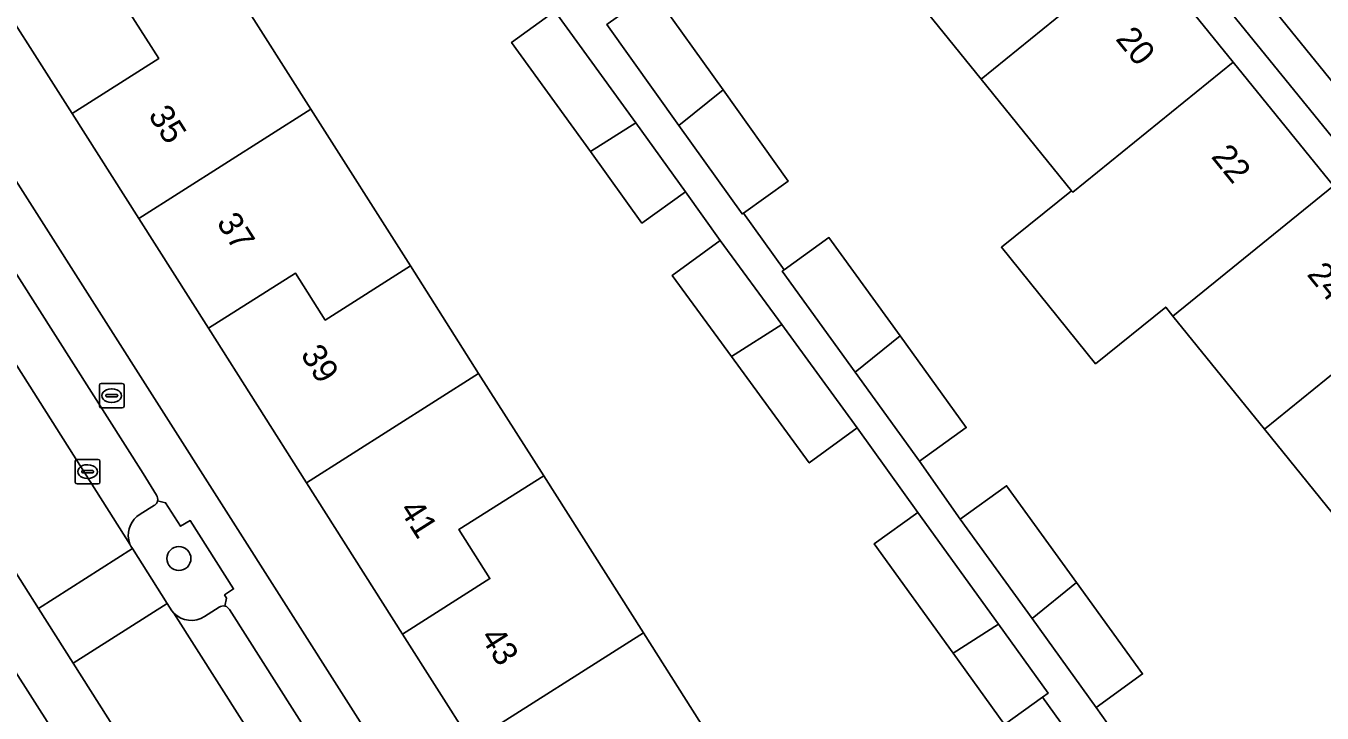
# Model space of a CAD drawing. Extents: x 162344 to 162869, y 381217 to 381818.
# Drawn here: x 162502.3 to 162555.1, y 381598.8 to 381626.8 of the extents above; entities that cross this region are included whole.
import ezdxf

# ---------------------------------------------------------------- set-up
doc = ezdxf.new("R2010")
doc.units = 0
for name, color, linetype in [('IMGEO_Boom', 7, 'Continuous'), ('IMGEO_Brandkraan', 7, 'Continuous'), ('IMGEO_Erf', 7, 'Continuous'), ('IMGEO_Groenvoorziening', 7, 'Continuous'), ('IMGEO_Kolk', 7, 'Continuous'), ('IMGEO_Pand', 7, 'Continuous'), ('IMGEO_Pand_nummerreeks', 7, 'Continuous'), ('IMGEO_Parkeervlak_open', 7, 'Continuous'), ('IMGEO_Rijbaan_lokaal_gesloten', 7, 'Continuous'), ('IMGEO_Rijbaan_lokaal_open', 7, 'Continuous'), ('IMGEO_Voetpad_open', 7, 'Continuous')]:
    doc.layers.add(name, color=color, linetype=linetype)

msp = doc.modelspace()

# ---------------------------------------------------------------- linework, layer by layer
at = {"layer": 'IMGEO_Boom'}
msp.add_circle((162508.528, 381605.122), 0.489, dxfattribs=at)
at = {"layer": 'IMGEO_Brandkraan'}
for p, q in [((162505.293, 381611.33), (162505.293, 381612.182)), ((162505.368, 381612.256), (162506.22, 381612.256)), ((162505.781, 381612.036), (162505.806, 381612.036)), ((162506.294, 381612.182), (162506.294, 381611.33)), ((162505.552, 381611.75), (162505.552, 381611.762)), ((162505.99, 381611.713), (162505.592, 381611.713)), ((162505.595, 381611.799), (162505.993, 381611.799)), ((162505.804, 381611.476), (162505.779, 381611.476)), ((162506.036, 381611.762), (162506.036, 381611.75)), ((162506.22, 381611.256), (162505.368, 381611.256))]:
    msp.add_line(p, q, dxfattribs=at)
for points in [[(162505.293, 381611.33), (162505.293, 381612.182)], [(162505.368, 381612.256), (162506.22, 381612.256)], [(162506.294, 381612.182), (162506.294, 381611.33)], [(162506.22, 381611.256), (162505.368, 381611.256)]]:
    msp.add_lwpolyline(points, dxfattribs=at)
for centre, radius, start, end in [((162505.37, 381612.18), 0.0765, 91.552, 178.448), ((162505.37, 381612.18), 0.0765, 91.552, 178.448), ((162506.218, 381612.18), 0.0765, 1.552, 88.448), ((162506.218, 381612.18), 0.0765, 1.552, 88.448), ((162505.592, 381611.759), 0.0403, 85.8775, 175.7526), ((162505.589, 381611.749), 0.0366, 178.938, 274.7102), ((162505.993, 381611.756), 0.043, 264.8664, 352.4533), ((162505.997, 381611.761), 0.0386, 1.7309, 96.639), ((162505.37, 381611.332), 0.0765, 181.552, 268.448), ((162505.37, 381611.332), 0.0765, 181.552, 268.448), ((162506.218, 381611.332), 0.0765, 271.552, 358.448), ((162506.218, 381611.332), 0.0765, 271.552, 358.448)]:
    msp.add_arc(centre, radius, start, end, dxfattribs=at)
for centre, major_axis, ratio, start_param, end_param in [((162505.78, 381611.756), (-0.387, 0.002), 0.722429, 4.712389, 7.853982), ((162505.805, 381611.756), (-0.39, 0.002), 0.717154, 1.570796, 4.712389)]:
    msp.add_ellipse(centre, major_axis=major_axis, ratio=ratio, start_param=start_param, end_param=end_param, dxfattribs=at)
at = {"layer": 'IMGEO_Erf'}
for points in [[(162513.38, 381674.107), (162512.565, 381673.447), (162516.63, 381668.417), (162520.622, 381663.477), (162524.355, 381658.858), (162528.316, 381653.955), (162532.138, 381649.227), (162536.056, 381644.377), (162539.798, 381639.748), (162543.769, 381634.833), (162547.709, 381629.957), (162551.438, 381625.343), (162555.512, 381620.301), (162559.239, 381615.69), (162563.247, 381610.73), (162566.934, 381606.168), (162570.843, 381601.33), (162571.832, 381602.129)], [(162509.729, 381614.501), (162506.891, 381618.974), (162504.179, 381623.249), (162500.254, 381629.436), (162496.21, 381635.81), (162493.518, 381640.054), (162490.785, 381644.361), (162486.625, 381650.919), (162483.717, 381649.074), (162500, 381623.471), (162531.035, 381574.671), (162533.863, 381576.458), (162531.166, 381580.71), (162527.169, 381587.01), (162523.206, 381593.256), (162520.428, 381597.636), (162517.63, 381602.045), (162513.719, 381608.21)], [(162500, 381603.428), (162482.857, 381630.326), (162481.918, 381629.814), (162481.958, 381629.752), (162482.007, 381629.783), (162485.338, 381624.533), (162488.628, 381619.345), (162491.92, 381614.157), (162495.211, 381608.969), (162498.502, 381603.78), (162501.793, 381598.593), (162505.084, 381593.404), (162508.375, 381588.216), (162511.667, 381583.028), (162514.958, 381577.839), (162518.25, 381572.651), (162521.79, 381567.07), (162522.773, 381567.696), (162522.094, 381568.761)]]:
    msp.add_lwpolyline(points, close=True, dxfattribs=at)
for points in [[(162509.92, 381629.7), (162513.898, 381623.43), (162517.95, 381617.043), (162520.727, 381612.666), (162523.373, 381608.497), (162527.437, 381602.092), (162531.429, 381595.8)], [(162556.718, 381605.428), (162552.71, 381610.388), (162548.983, 381614.999), (162548.688, 381615.364), (162545.837, 381613.06), (162542.005, 381617.803), (162544.856, 381620.107), (162541.181, 381624.654), (162537.239, 381629.531)], [(162527.821, 381628.216), (162530.674, 381624.218), (162533.328, 381620.5), (162531.501, 381619.196), (162533.154, 381616.877), (162534.984, 381618.198), (162537.875, 381614.19), (162540.57, 381610.455), (162538.67, 381609.084), (162540.325, 381606.725), (162542.212, 381608.087), (162545.056, 381604.145), (162547.745, 381600.418), (162545.859, 381599.057), (162547.476, 381596.777), (162549.379, 381598.143), (162552.266, 381594.122), (162554.849, 381590.523), (162555.13, 381590.715)], [(162545.066, 381597.532), (162543.669, 381599.469), (162542.134, 381598.362), (162540.035, 381601.272), (162536.826, 381605.721), (162538.594, 381606.997), (162536.135, 381610.447), (162534.179, 381609.019), (162531.014, 381613.356), (162528.606, 381616.655), (162530.562, 381618.083), (162529.142, 381620.065), (162527.374, 381618.79), (162525.275, 381621.701), (162522.066, 381626.149), (162523.834, 381627.425)]]:
    msp.add_lwpolyline(points, dxfattribs=at)
at = {"layer": 'IMGEO_Groenvoorziening'}
for points in [[(162507.534, 381607.289), (162506.945, 381606.925)], [(162508.988, 381606.666), (162508.597, 381606.435), (162507.987, 381607.394), (162507.655, 381607.466)], [(162510.402, 381603.182), (162510.461, 381603.501), (162510.386, 381603.641), (162510.756, 381603.885), (162508.988, 381606.666)], [(162506.486, 381605.887), (162506.536, 381605.712), (162506.577, 381605.621), (162506.636, 381605.528), (162508.054, 381603.286), (162508.241, 381602.992), (162508.323, 381602.896)], [(162509.573, 381602.758), (162510.171, 381603.135)]]:
    msp.add_lwpolyline(points, dxfattribs=at)
for centre, radius, start, end in [((162507.349, 381607.545), 0.316, 305.8309, 345.4549), ((162507.463, 381606.075), 0.995, 121.369, 190.9213), ((162510.337, 381602.91), 0.279, 76.5428, 126.4584), ((162509.033, 381603.594), 0.995, 224.5213, 302.8788)]:
    msp.add_arc(centre, radius, start, end, dxfattribs=at)
at = {"layer": 'IMGEO_Kolk'}
for p, q in [((162504.312, 381608.236), (162504.312, 381609.088)), ((162504.387, 381609.162), (162505.239, 381609.162)), ((162504.8, 381608.942), (162504.825, 381608.942)), ((162505.313, 381609.088), (162505.313, 381608.236)), ((162504.571, 381608.656), (162504.571, 381608.668)), ((162505.009, 381608.619), (162504.611, 381608.619)), ((162504.614, 381608.705), (162505.012, 381608.705)), ((162504.823, 381608.382), (162504.798, 381608.382)), ((162505.055, 381608.668), (162505.055, 381608.656)), ((162505.239, 381608.162), (162504.387, 381608.162))]:
    msp.add_line(p, q, dxfattribs=at)
for points in [[(162504.312, 381608.236), (162504.312, 381609.088)], [(162504.387, 381609.162), (162505.239, 381609.162)], [(162505.313, 381609.088), (162505.313, 381608.236)], [(162505.239, 381608.162), (162504.387, 381608.162)]]:
    msp.add_lwpolyline(points, dxfattribs=at)
for centre, radius, start, end in [((162504.389, 381609.086), 0.0765, 91.552, 178.448), ((162504.389, 381609.086), 0.0765, 91.552, 178.448), ((162505.237, 381609.086), 0.0765, 1.552, 88.448), ((162505.237, 381609.086), 0.0765, 1.552, 88.448), ((162504.611, 381608.665), 0.0403, 85.8775, 175.7526), ((162504.608, 381608.655), 0.0366, 178.938, 274.7102), ((162505.012, 381608.662), 0.043, 264.8664, 352.4533), ((162505.016, 381608.667), 0.0386, 1.7309, 96.639), ((162504.389, 381608.238), 0.0765, 181.552, 268.448), ((162504.389, 381608.238), 0.0765, 181.552, 268.448), ((162505.237, 381608.238), 0.0765, 271.552, 358.448), ((162505.237, 381608.238), 0.0765, 271.552, 358.448)]:
    msp.add_arc(centre, radius, start, end, dxfattribs=at)
for centre, major_axis, ratio, start_param, end_param in [((162504.799, 381608.662), (-0.387, 0.002), 0.722429, 4.712389, 7.853982), ((162504.824, 381608.662), (-0.39, 0.002), 0.717154, 1.570796, 4.712389)]:
    msp.add_ellipse(centre, major_axis=major_axis, ratio=ratio, start_param=start_param, end_param=end_param, dxfattribs=at)
at = {"layer": 'IMGEO_Pand'}
for points in [[(162547.709, 381629.957), (162543.769, 381634.833), (162537.239, 381629.531), (162541.181, 381624.654)], [(162509.92, 381629.7), (162507.26, 381633.892), (162500.254, 381629.436), (162504.179, 381623.249), (162507.708, 381625.494), (162506.441, 381627.488)], [(162551.438, 381625.343), (162547.709, 381629.957), (162541.181, 381624.654), (162544.856, 381620.107), (162544.909, 381620.041)], [(162509.92, 381629.7), (162506.441, 381627.488), (162507.708, 381625.494), (162504.179, 381623.249), (162506.891, 381618.974), (162513.898, 381623.43)], [(162526, 381626.917), (162525.943, 381626.876), (162528.879, 381622.762), (162530.674, 381624.218), (162527.821, 381628.216)], [(162525.275, 381621.701), (162527.117, 381622.873), (162523.834, 381627.425), (162522.066, 381626.149)], [(162555.512, 381620.301), (162551.438, 381625.343), (162544.909, 381620.041), (162544.856, 381620.107), (162542.005, 381617.803), (162545.837, 381613.06), (162548.688, 381615.364), (162548.983, 381614.999)], [(162530.674, 381624.218), (162528.879, 381622.762), (162531.45, 381619.16), (162531.501, 381619.196), (162533.328, 381620.5)], [(162513.898, 381623.43), (162506.891, 381618.974), (162509.729, 381614.501), (162513.267, 381616.751), (162514.483, 381614.838), (162517.95, 381617.043)], [(162525.275, 381621.701), (162527.374, 381618.79), (162529.142, 381620.065), (162527.117, 381622.873)], [(162559.239, 381615.69), (162555.512, 381620.301), (162548.983, 381614.999), (162552.71, 381610.388)], [(162530.562, 381618.083), (162528.606, 381616.655), (162531.014, 381613.356), (162533.062, 381614.658)], [(162533.154, 381616.877), (162533.084, 381616.827), (162536.054, 381612.711), (162537.875, 381614.19), (162534.984, 381618.198)], [(162517.95, 381617.043), (162514.483, 381614.838), (162513.267, 381616.751), (162509.729, 381614.501), (162513.719, 381608.21), (162520.727, 381612.666)], [(162563.247, 381610.73), (162559.239, 381615.69), (162552.71, 381610.388), (162556.718, 381605.428)], [(162533.062, 381614.658), (162531.014, 381613.356), (162534.179, 381609.019), (162536.135, 381610.447)], [(162537.875, 381614.19), (162536.054, 381612.711), (162538.67, 381609.084), (162540.57, 381610.455)], [(162523.373, 381608.497), (162520.727, 381612.666), (162513.719, 381608.21), (162517.63, 381602.045), (162521.182, 381604.304), (162519.915, 381606.298)], [(162523.373, 381608.497), (162519.915, 381606.298), (162521.182, 381604.304), (162517.63, 381602.045), (162520.428, 381597.636), (162527.437, 381602.092)], [(162540.325, 381606.725), (162543.247, 381602.676), (162545.056, 381604.145), (162542.212, 381608.087)], [(162540.035, 381601.272), (162541.878, 381602.444), (162538.594, 381606.997), (162536.826, 381605.721)], [(162545.056, 381604.145), (162543.247, 381602.676), (162545.859, 381599.057), (162547.745, 381600.418)], [(162527.437, 381602.092), (162520.428, 381597.636), (162523.206, 381593.256), (162526.767, 381595.521), (162527.983, 381593.608), (162531.429, 381595.8)], [(162541.878, 381602.444), (162540.035, 381601.272), (162542.134, 381598.362), (162543.669, 381599.469), (162543.902, 381599.637)]]:
    msp.add_lwpolyline(points, close=True, dxfattribs=at)
at = {"layer": 'IMGEO_Parkeervlak_open'}
for points in [[(162507.62, 381607.705), (162507.07, 381608.592), (162496.361, 381625.451)], [(162494.37, 381624.906), (162506.536, 381605.712), (162506.486, 381605.887)], [(162506.945, 381606.925), (162507.534, 381607.289)], [(162510.171, 381603.135), (162509.573, 381602.758)], [(162527.735, 381576.018), (162510.585, 381603.042)], [(162508.323, 381602.896), (162527.79, 381572.233)]]:
    msp.add_lwpolyline(points, dxfattribs=at)
for centre, radius, start, end in [((162507.349, 381607.545), 0.316, 305.8309, 345.4549), ((162507.346, 381607.543), 0.319, 346.0728, 30.5899), ((162507.463, 381606.075), 0.995, 121.369, 190.9213), ((162510.337, 381602.91), 0.279, 76.5428, 126.4584), ((162510.338, 381602.908), 0.281, 28.385, 76.781), ((162509.033, 381603.594), 0.995, 224.5213, 302.8788)]:
    msp.add_arc(centre, radius, start, end, dxfattribs=at)
at = {"layer": 'IMGEO_Rijbaan_lokaal_gesloten'}
msp.add_lwpolyline([(162506.636, 381605.528), (162502.811, 381603.082), (162504.221, 381600.859), (162508.054, 381603.286)], close=True, dxfattribs=at)
at = {"layer": 'IMGEO_Rijbaan_lokaal_open'}
for points in [[(162473.904, 381648.571), (162474.039, 381648.375), (162474.586, 381647.556), (162480.538, 381638.212), (162482.235, 381635.536), (162491.687, 381620.613), (162500.464, 381606.783), (162502.811, 381603.082), (162506.636, 381605.528), (162506.577, 381605.621), (162506.536, 381605.712), (162494.37, 381624.906), (162494.322, 381624.959), (162493.957, 381625.539), (162477.262, 381651.857)], [(162593.104, 381583.166), (162592.337, 381584.135), (162588.977, 381588.297), (162588.864, 381588.438), (162577.813, 381602.191), (162577.762, 381602.246), (162574.68, 381606.059), (162574.574, 381606.188), (162573.231, 381607.826), (162555.033, 381630.367), (162552.464, 381628.263), (162557.077, 381622.564), (162568.008, 381609.06), (162573.172, 381602.64), (162576.33, 381598.754), (162579.594, 381594.706), (162585.923, 381586.92), (162590.428, 381581.301)]]:
    msp.add_lwpolyline(points, dxfattribs=at)
msp.add_lwpolyline([(162508.323, 381602.896), (162508.241, 381602.992), (162508.054, 381603.286), (162504.221, 381600.859), (162509.771, 381592.107), (162519.683, 381576.506), (162528.482, 381562.594), (162533.548, 381554.605), (162536.173, 381550.404), (162540.033, 381552.852), (162539.912, 381553.029), (162531.859, 381565.804), (162530.041, 381568.705), (162527.79, 381572.233)], close=True, dxfattribs=at)
at = {"layer": 'IMGEO_Voetpad_open'}
for points in [[(162508.84, 381681.944), (162504.138, 381678.21), (162505.063, 381677.02), (162508.656, 381679.88), (162512.571, 381675.042), (162508.995, 381672.145), (162508.914, 381672.079), (162509.05, 381671.905), (162509.673, 381671.105), (162512.565, 381673.447), (162513.38, 381674.107), (162571.832, 381602.129), (162570.843, 381601.33), (162571.787, 381600.176), (162573.538, 381598.034), (162573.688, 381597.851), (162577.947, 381592.831), (162582.764, 381586.934), (162583.699, 381585.765), (162585.923, 381586.92), (162579.594, 381594.706), (162576.33, 381598.754)], [(162576.33, 381598.754), (162575.4, 381598.003), (162572.268, 381601.906), (162573.172, 381602.64), (162568.008, 381609.06), (162557.077, 381622.564), (162552.464, 381628.263), (162550.263, 381630.982), (162546.437, 381635.708), (162536.447, 381648.07), (162524.281, 381663.125), (162512.103, 381678.261), (162509.921, 381680.927)], [(162472.704, 381650.202), (162472.225, 381650.761), (162464.301, 381660.45), (162461.143, 381664.345), (162453.433, 381673.852), (162452.016, 381672.565), (162460.935, 381661.289), (162471.067, 381648.837), (162472.56, 381646.493), (162481.795, 381631.988), (162482.857, 381630.326), (162500, 381603.428), (162522.094, 381568.761), (162522.773, 381567.696), (162523.584, 381566.423), (162523.028, 381566.054), (162525.538, 381562.087), (162528.355, 381557.526), (162532.073, 381550.22), (162532.638, 381549.091), (162533.893, 381543.857)], [(162536.254, 381572.675), (162534.661, 381575.207), (162533.863, 381576.458), (162531.035, 381574.671), (162500, 381623.471), (162483.717, 381649.074), (162486.625, 381650.919), (162489.805, 381652.936), (162488.804, 381654.132), (162487.93, 381655.177), (162482.537, 381650.933), (162479.032, 381656.467), (162483.97, 381660.263), (162483.121, 381661.563), (162478.205, 381657.739), (162476.197, 381660.891)], [(162536.173, 381550.404), (162533.548, 381554.605), (162528.482, 381562.594), (162519.683, 381576.506), (162509.771, 381592.107), (162504.221, 381600.859), (162502.811, 381603.082), (162500.464, 381606.783), (162491.687, 381620.613), (162482.235, 381635.536), (162480.538, 381638.212), (162479.529, 381637.56), (162475.997, 381643.106), (162473.959, 381646.306)], [(162523.834, 381627.425), (162527.117, 381622.873), (162529.142, 381620.065), (162530.562, 381618.083), (162533.062, 381614.658), (162536.135, 381610.447), (162538.594, 381606.997), (162541.878, 381602.444), (162543.902, 381599.637), (162543.669, 381599.469), (162545.066, 381597.532)], [(162555.13, 381590.715), (162554.849, 381590.523), (162552.947, 381589.157), (162550.444, 381592.644), (162547.476, 381596.777), (162545.859, 381599.057), (162543.247, 381602.676), (162540.325, 381606.725), (162538.67, 381609.084), (162536.054, 381612.711), (162533.084, 381616.827), (162533.154, 381616.877), (162531.501, 381619.196), (162531.45, 381619.16), (162528.879, 381622.762), (162525.943, 381626.876)], [(162496.361, 381625.451), (162507.07, 381608.592), (162507.62, 381607.705)], [(162507.655, 381607.466), (162507.987, 381607.394), (162508.597, 381606.435), (162508.988, 381606.666), (162510.756, 381603.885), (162510.386, 381603.641), (162510.461, 381603.501), (162510.402, 381603.182)], [(162510.585, 381603.042), (162527.735, 381576.018)]]:
    msp.add_lwpolyline(points, dxfattribs=at)
for centre, radius, start, end in [((162507.346, 381607.543), 0.319, 346.0728, 30.5899), ((162510.338, 381602.908), 0.281, 28.385, 76.781)]:
    msp.add_arc(centre, radius, start, end, dxfattribs=at)

# ---------------------------------------------------------------- texts
at = {"layer": 'IMGEO_Pand_nummerreeks'}
for s, rotation, p in [('20', 309.0755, (162546.618, 381626.277)), ('35', 302.4521, (162507.256, 381623.185)), ('22', 309.0755, (162550.508, 381621.484)), ('37', 302.4521, (162510.035, 381618.814)), ('24', 309.0755, (162554.405, 381616.686)), ('39', 302.4521, (162513.455, 381613.435)), ('41', 302.4521, (162517.474, 381607.116)), ('43', 302.4521, (162520.772, 381601.927))]:
    msp.add_text(s, height=1, rotation=rotation, dxfattribs=at).set_placement(p)

doc.saveas('drawing.dxf')
